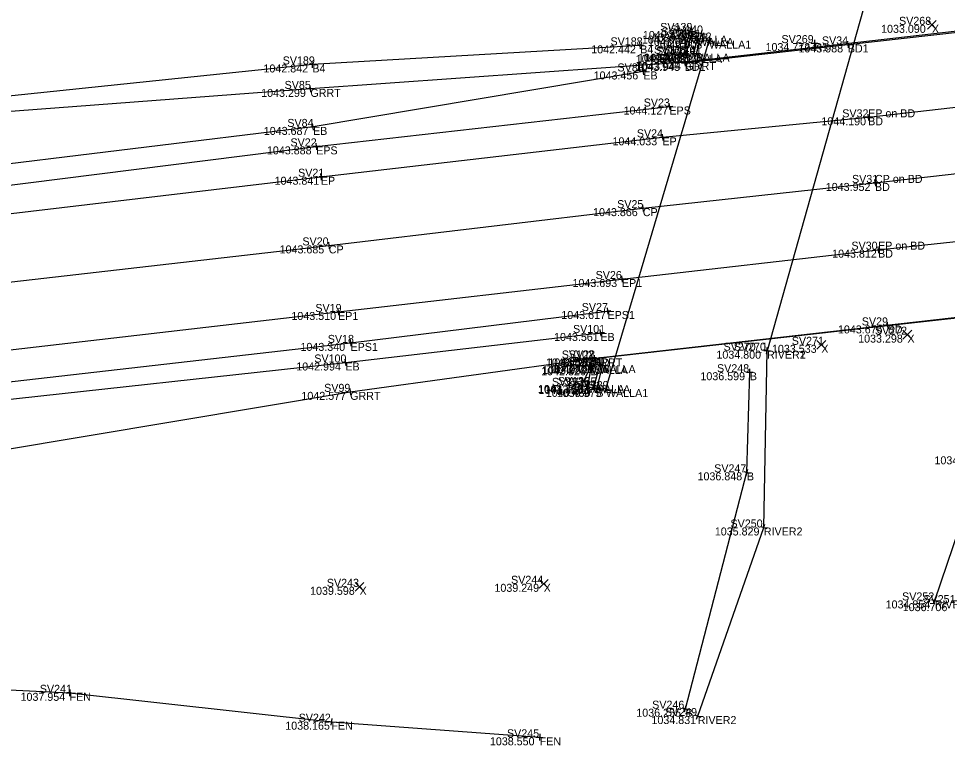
# Model space of a CAD drawing. Extents: x 1542529 to 1609210, y 587215 to 645373.
# Drawn here: x 1608791 to 1608930.2, y 645166.5 to 645275.5 of the extents above; entities that cross this region are included whole.
import ezdxf

# ---------------------------------------------------------------- set-up
doc = ezdxf.new("R2010")
doc.units = 0
for name, color, linetype in [('BR_X_SV_Abut', 7, 'Continuous'), ('BR_X_SV_Abut_Text', 7, 'Continuous'), ('BR_X_SV_Deck_Top', 7, 'Continuous'), ('BR_X_SV_Deck_Top_Text', 7, 'Continuous'), ('HY_X_Water_Edge', 7, 'Continuous'), ('PV_X_COP', 7, 'Continuous'), ('PV_X_EOP', 7, 'Continuous'), ('PV_X_Shoulder', 7, 'Continuous'), ('PV_X_Shoulder_Aggregate', 7, 'Continuous'), ('RD_X_Fence', 7, 'Continuous'), ('RD_X_GR_Rt', 7, 'Continuous'), ('SV_X_Break_Lines', 7, 'Continuous'), ('SV_X_Random_Point', 7, 'Continuous'), ('SV_X_Shot_Marker', 7, 'Continuous'), ('SV_X_Text_Comment', 7, 'Continuous'), ('SV_X_Text_Elevation', 7, 'Continuous'), ('SV_X_Text_Name', 7, 'Continuous')]:
    doc.layers.add(name, color=color, linetype=linetype)

msp = doc.modelspace()

# ---------------------------------------------------------------- linework, layer by layer
at = {"layer": 'BR_X_SV_Abut'}
for points in [[(1608879.02, 645219.91), (1608894.47, 645272.17)], [(1608890.97, 645270.03), (1608891.79, 645272.91), (1608892.73, 645272.57), (1608892.12, 645270.19)], [(1608878.03, 645223.49), (1608877.23, 645220.46), (1608876.34, 645220.52), (1608876.85, 645223.37)]]:
    msp.add_lwpolyline(points, dxfattribs=at)
at = {"layer": 'BR_X_SV_Abut_Text'}
for p, q in [((1608891.31, 645273.05), (1608892.27, 645272.78)), ((1608891.65, 645272.43), (1608891.92, 645273.39)), ((1608892.9, 645273.04), (1608892.56, 645272.1)), ((1608891.79, 645272.91), (1608891.79, 645272.91)), ((1608892.26, 645272.74), (1608893.2, 645272.4)), ((1608892.73, 645272.57), (1608892.73, 645272.57)), ((1608893.99, 645272.31), (1608894.95, 645272.03)), ((1608894.33, 645271.69), (1608894.61, 645272.65)), ((1608894.47, 645272.17), (1608894.47, 645272.17)), ((1608890.49, 645270.17), (1608891.45, 645269.89)), ((1608890.83, 645269.55), (1608891.1, 645270.51)), ((1608892.6, 645270.07), (1608891.64, 645270.32)), ((1608892.24, 645270.68), (1608892, 645269.71)), ((1608892.12, 645270.19), (1608892.12, 645270.19)), ((1608890.97, 645270.03), (1608890.97, 645270.03)), ((1608876.36, 645223.46), (1608877.34, 645223.28)), ((1608876.76, 645222.88), (1608876.94, 645223.86)), ((1608876.85, 645223.37), (1608876.85, 645223.37)), ((1608878.51, 645223.36), (1608877.54, 645223.62)), ((1608878.15, 645223.97), (1608877.9, 645223.01)), ((1608878.03, 645223.49), (1608878.03, 645223.49)), ((1608876.84, 645220.49), (1608875.84, 645220.54)), ((1608876.31, 645220.02), (1608876.37, 645221.01)), ((1608876.34, 645220.52), (1608876.34, 645220.52)), ((1608877.72, 645220.34), (1608876.75, 645220.59)), ((1608877.36, 645220.95), (1608877.11, 645219.98)), ((1608877.23, 645220.46), (1608877.23, 645220.46)), ((1608878.54, 645220.05), (1608879.5, 645219.77)), ((1608878.88, 645219.43), (1608879.16, 645220.39)), ((1608879.02, 645219.91), (1608879.02, 645219.91))]:
    msp.add_line(p, q, dxfattribs=at)
at = {"layer": 'BR_X_SV_Deck_Top'}
for points in [[(1608890.83, 645268.82), (1608915.28, 645271.59), (1608953.53, 645275.9), (1608984.83, 645279.39)], [(1608887.49, 645257.66), (1608918.33, 645260.66), (1608954.65, 645264.83), (1608980.54, 645267.46)], [(1608884.55, 645247.04), (1608919.35, 645250.82), (1608955.34, 645254.95), (1608977.96, 645256.77)], [(1608881.41, 645236.41), (1608919.82, 645240.81), (1608956.22, 645244.69), (1608975.06, 645246.73)], [(1608877.31, 645224.5), (1608921.25, 645229.45), (1608957.31, 645233.44), (1608971.94, 645235.23)]]:
    msp.add_lwpolyline(points, dxfattribs=at)
at = {"layer": 'BR_X_SV_Deck_Top_Text'}
for p, q in [((1608914.78, 645271.53), (1608915.78, 645271.65)), ((1608915.22, 645272.09), (1608915.34, 645271.09)), ((1608915.28, 645271.59), (1608915.28, 645271.59)), ((1608890.33, 645268.77), (1608891.32, 645268.88)), ((1608890.77, 645269.32), (1608890.88, 645268.33)), ((1608890.83, 645268.82), (1608890.83, 645268.82)), ((1608917.83, 645260.61), (1608918.83, 645260.71)), ((1608918.28, 645261.15), (1608918.38, 645260.16)), ((1608918.33, 645260.66), (1608918.33, 645260.66)), ((1608918.86, 645250.77), (1608919.85, 645250.88)), ((1608919.3, 645251.32), (1608919.41, 645250.32)), ((1608919.35, 645250.82), (1608919.35, 645250.82)), ((1608919.76, 645241.31), (1608919.87, 645240.31)), ((1608919.32, 645240.75), (1608920.31, 645240.87)), ((1608919.82, 645240.81), (1608919.82, 645240.81)), ((1608921.19, 645229.94), (1608921.3, 645228.95)), ((1608920.75, 645229.39), (1608921.74, 645229.5)), ((1608921.25, 645229.45), (1608921.25, 645229.45)), ((1608876.82, 645224.44), (1608877.81, 645224.55)), ((1608877.26, 645225), (1608877.37, 645224)), ((1608877.31, 645224.5), (1608877.31, 645224.5))]:
    msp.add_line(p, q, dxfattribs=at)
at = {"layer": 'HY_X_Water_Edge'}
for points in [[(1608927.27, 645323.87), (1608921.03, 645295.76), (1608920.78, 645288.24), (1608903.17, 645225.66)], [(1608928.31, 645188.21), (1608935.69, 645209.82), (1608940.9, 645230.56)], [(1608892.78, 645170.87), (1608902.69, 645199.15), (1608903.17, 645225.66)]]:
    msp.add_lwpolyline(points, dxfattribs=at)
at = {"layer": 'PV_X_COP'}
msp.add_lwpolyline([(1608671.55, 645219.6), (1608727.32, 645227.68), (1608782.03, 645235.07), (1608837.47, 645241.45), (1608884.55, 645247.04)], dxfattribs=at)
at = {"layer": 'PV_X_EOP'}
for points in [[(1608669.93, 645230.13), (1608725.82, 645238.07), (1608781.37, 645245.23), (1608836.27, 645251.75), (1608887.49, 645257.66)], [(1608672.74, 645209.93), (1608728.42, 645217.7), (1608783.22, 645225.06), (1608838.86, 645231.47), (1608881.41, 645236.41)]]:
    msp.add_lwpolyline(points, dxfattribs=at)
at = {"layer": 'PV_X_Shoulder'}
for points in [[(1608669.52, 645234.3), (1608724.97, 645242.37), (1608781.24, 645249.44), (1608835.57, 645256.3), (1608888.53, 645262.28)], [(1608672.97, 645206.8), (1608729.46, 645213.9), (1608783.39, 645220.28), (1608840.72, 645226.83), (1608879.25, 645231.61)]]:
    msp.add_lwpolyline(points, dxfattribs=at)
at = {"layer": 'PV_X_Shoulder_Aggregate'}
for points in [[(1608884.62, 645267.54), (1608835.11, 645259.22), (1608780.98, 645252.63), (1608724.64, 645244.99), (1608669.45, 645236.36)], [(1608673.57, 645203.81), (1608730.4, 645211.29), (1608784.18, 645217.8), (1608839.95, 645223.89), (1608878.18, 645228.32)]]:
    msp.add_lwpolyline(points, dxfattribs=at)
at = {"layer": 'RD_X_Fence'}
msp.add_lwpolyline([(1608683.09, 645172.08), (1608726.62, 645177.95), (1608798.6, 645174.35), (1608837.85, 645170.02), (1608869.08, 645167.68)], dxfattribs=at)
at = {"layer": 'RD_X_GR_Rt'}
for p, q in [((1608987.41, 645279.9), (1608890.95, 645268.94)), ((1608890.95, 645268.94), (1608834.71, 645264.92)), ((1608834.71, 645264.92), (1608779.9, 645260.78)), ((1608876.93, 645224.49), (1608971.87, 645235.28)), ((1608840.67, 645219.49), (1608876.93, 645224.49)), ((1608785.12, 645210.19), (1608840.67, 645219.49))]:
    msp.add_line(p, q, dxfattribs=at)
at = {"layer": 'SV_X_Break_Lines'}
for points in [[(1608890.69, 645270.2), (1608891.62, 645273.61), (1608893.3, 645273.23), (1608892.55, 645270.19)], [(1608884.15, 645271.45), (1608835, 645268.59), (1608778.42, 645262.67), (1608720.98, 645258.97), (1608666.54, 645249.78)], [(1608878.52, 645223.49), (1608877.58, 645219.94), (1608875.37, 645220.39), (1608876.7, 645223.17)], [(1608890.93, 645171.97), (1608900.15, 645207.42), (1608900.59, 645222.43)]]:
    msp.add_lwpolyline(points, dxfattribs=at)
at = {"layer": 'SV_X_Random_Point'}
for p, q in [((1608927.22, 645273.86), (1608928.55, 645275.2)), ((1608927.22, 645275.2), (1608928.55, 645273.86)), ((1608923.55, 645227.4), (1608924.89, 645228.74)), ((1608923.55, 645228.74), (1608924.89, 645227.4)), ((1608910.64, 645225.87), (1608911.97, 645227.21)), ((1608910.64, 645227.21), (1608911.97, 645225.87)), ((1608841.4, 645189.58), (1608842.74, 645190.91)), ((1608841.4, 645190.91), (1608842.74, 645189.58)), ((1608869.01, 645190.03), (1608870.35, 645191.37)), ((1608869.01, 645191.37), (1608870.35, 645190.03))]:
    msp.add_line(p, q, dxfattribs=at)
at = {"layer": 'SV_X_Shot_Marker'}
for p, q in [((1608891.14, 645273.74), (1608892.11, 645273.47)), ((1608891.49, 645273.12), (1608891.76, 645274.09)), ((1608891.62, 645273.61), (1608891.62, 645273.61)), ((1608892.82, 645273.34), (1608893.79, 645273.12)), ((1608893.41, 645273.72), (1608893.19, 645272.74)), ((1608893.3, 645273.23), (1608893.3, 645273.23)), ((1608884.18, 645270.95), (1608884.12, 645271.95)), ((1608909.77, 645271.79), (1608910.77, 645271.79)), ((1608910.27, 645272.29), (1608910.27, 645271.29)), ((1608910.27, 645271.79), (1608910.27, 645271.79)), ((1608884.65, 645271.48), (1608883.65, 645271.42)), ((1608884.15, 645271.45), (1608884.15, 645271.45)), ((1608890.21, 645270.33), (1608891.18, 645270.06)), ((1608890.56, 645269.71), (1608890.82, 645270.68)), ((1608890.69, 645270.2), (1608890.69, 645270.2)), ((1608893.04, 645270.07), (1608892.07, 645270.3)), ((1608892.67, 645270.67), (1608892.43, 645269.7)), ((1608892.55, 645270.19), (1608892.55, 645270.19)), ((1608835.03, 645268.09), (1608834.97, 645269.09)), ((1608891.45, 645268.97), (1608890.45, 645268.9)), ((1608890.98, 645268.44), (1608890.91, 645269.44)), ((1608890.95, 645268.94), (1608890.95, 645268.94)), ((1608835.5, 645268.62), (1608834.5, 645268.56)), ((1608835, 645268.59), (1608835, 645268.59)), ((1608885.12, 645267.63), (1608884.13, 645267.46)), ((1608884.7, 645267.05), (1608884.54, 645268.04)), ((1608884.62, 645267.54), (1608884.62, 645267.54)), ((1608835.21, 645264.95), (1608834.21, 645264.88)), ((1608834.75, 645264.42), (1608834.67, 645265.42)), ((1608834.71, 645264.92), (1608834.71, 645264.92)), ((1608888.03, 645262.22), (1608889.03, 645262.34)), ((1608888.47, 645262.78), (1608888.59, 645261.78)), ((1608888.53, 645262.28), (1608888.53, 645262.28)), ((1608835.6, 645259.3), (1608834.62, 645259.14)), ((1608835.19, 645258.73), (1608835.03, 645259.72)), ((1608835.11, 645259.22), (1608835.11, 645259.22)), ((1608886.99, 645257.61), (1608887.99, 645257.71)), ((1608887.44, 645258.15), (1608887.54, 645257.16)), ((1608887.49, 645257.66), (1608887.49, 645257.66)), ((1608835.07, 645256.24), (1608836.07, 645256.36)), ((1608835.51, 645256.8), (1608835.63, 645255.8)), ((1608835.57, 645256.3), (1608835.57, 645256.3)), ((1608836.21, 645252.24), (1608836.33, 645251.25)), ((1608835.77, 645251.69), (1608836.76, 645251.81)), ((1608836.27, 645251.75), (1608836.27, 645251.75)), ((1608884.06, 645246.99), (1608885.05, 645247.1)), ((1608884.5, 645247.54), (1608884.61, 645246.55)), ((1608884.55, 645247.04), (1608884.55, 645247.04)), ((1608836.98, 645241.39), (1608837.97, 645241.51)), ((1608837.42, 645241.95), (1608837.53, 645240.95)), ((1608837.47, 645241.45), (1608837.47, 645241.45)), ((1608881.35, 645236.91), (1608881.46, 645235.92)), ((1608880.91, 645236.36), (1608881.9, 645236.47)), ((1608881.41, 645236.41), (1608881.41, 645236.41)), ((1608838.37, 645231.41), (1608839.36, 645231.53)), ((1608838.81, 645231.97), (1608838.92, 645230.97)), ((1608838.86, 645231.47), (1608838.86, 645231.47)), ((1608878.75, 645231.55), (1608879.74, 645231.67)), ((1608879.19, 645232.11), (1608879.31, 645231.12)), ((1608879.25, 645231.61), (1608879.25, 645231.61)), ((1608878.12, 645228.82), (1608878.24, 645227.82)), ((1608840.66, 645227.33), (1608840.77, 645226.33)), ((1608877.68, 645228.26), (1608878.68, 645228.38)), ((1608878.18, 645228.32), (1608878.18, 645228.32)), ((1608840.22, 645226.77), (1608841.21, 645226.89)), ((1608840.72, 645226.83), (1608840.72, 645226.83)), ((1608902.67, 645225.67), (1608903.67, 645225.65)), ((1608903.65, 645225.52), (1608902.68, 645225.79)), ((1608903.3, 645226.14), (1608903.03, 645225.18)), ((1608903.16, 645225.16), (1608903.17, 645226.16)), ((1608903.17, 645225.66), (1608903.17, 645225.66)), ((1608903.17, 645225.66), (1608903.17, 645225.66)), ((1608839.89, 645224.38), (1608840, 645223.39)), ((1608876.43, 645224.43), (1608877.43, 645224.55)), ((1608876.87, 645224.99), (1608876.99, 645223.99)), ((1608876.93, 645224.49), (1608876.93, 645224.49)), ((1608839.45, 645223.83), (1608840.44, 645223.94)), ((1608839.95, 645223.89), (1608839.95, 645223.89)), ((1608876.25, 645223.38), (1608877.15, 645222.95)), ((1608876.49, 645222.72), (1608876.92, 645223.62)), ((1608876.7, 645223.17), (1608876.7, 645223.17)), ((1608879, 645223.36), (1608878.04, 645223.62)), ((1608878.65, 645223.97), (1608878.39, 645223.01)), ((1608878.52, 645223.49), (1608878.52, 645223.49)), ((1608900.57, 645221.93), (1608900.6, 645222.93)), ((1608900.09, 645222.45), (1608901.08, 645222.42)), ((1608900.59, 645222.43), (1608900.59, 645222.43)), ((1608875.86, 645220.29), (1608874.88, 645220.49)), ((1608875.27, 645219.9), (1608875.48, 645220.88)), ((1608875.37, 645220.39), (1608875.37, 645220.39)), ((1608878.06, 645219.81), (1608877.09, 645220.06)), ((1608877.71, 645220.42), (1608877.45, 645219.45)), ((1608840.18, 645219.42), (1608841.17, 645219.56)), ((1608840.6, 645219.99), (1608840.74, 645218.99)), ((1608840.67, 645219.49), (1608840.67, 645219.49)), ((1608877.58, 645219.94), (1608877.58, 645219.94)), ((1608899.67, 645207.54), (1608900.64, 645207.29)), ((1608900.03, 645206.93), (1608900.28, 645207.9)), ((1608900.15, 645207.42), (1608900.15, 645207.42)), ((1608902.22, 645199.31), (1608903.16, 645198.98)), ((1608902.53, 645198.67), (1608902.86, 645199.62)), ((1608902.69, 645199.15), (1608902.69, 645199.15)), ((1608927.83, 645188.37), (1608928.78, 645188.05)), ((1608928.15, 645187.74), (1608928.47, 645188.69)), ((1608928.31, 645188.21), (1608928.31, 645188.21)), ((1608798.1, 645174.37), (1608799.1, 645174.32)), ((1608798.62, 645174.84), (1608798.57, 645173.85)), ((1608798.6, 645174.35), (1608798.6, 645174.35)), ((1608890.44, 645172.1), (1608891.41, 645171.85)), ((1608890.8, 645171.49), (1608891.05, 645172.46)), ((1608890.93, 645171.97), (1608890.93, 645171.97)), ((1608892.61, 645170.4), (1608892.94, 645171.35)), ((1608837.35, 645170.07), (1608838.34, 645169.96)), ((1608837.9, 645170.51), (1608837.79, 645169.52)), ((1608837.85, 645170.02), (1608837.85, 645170.02)), ((1608892.3, 645171.04), (1608893.25, 645170.71)), ((1608892.78, 645170.87), (1608892.78, 645170.87)), ((1608868.58, 645167.72), (1608869.58, 645167.64)), ((1608869.12, 645168.18), (1608869.04, 645167.18)), ((1608869.08, 645167.68), (1608869.08, 645167.68))]:
    msp.add_line(p, q, dxfattribs=at)

# ---------------------------------------------------------------- texts
at = {"layer": 'BR_X_SV_Abut_Text'}
for s, p in [('SV144', (1608887.35, 645272.91)), ('SV145', (1608888.28, 645272.57)), ('SV142', (1608890.03, 645272.17)), ('1043.655', (1608884.4, 645271.71)), ('1043.649', (1608885.32, 645271.37)), ('1040.008', (1608886.77, 645270.97)), ('WALLA', (1608891.79, 645271.71)), ('WALLA', (1608892.73, 645271.37)), ('WALLA1', (1608894.47, 645270.97)), ('1043.723', (1608884.79, 645268.99)), ('SV143', (1608886.52, 645270.03)), ('SV146', (1608887.6, 645270.19)), ('WALLA', (1608892.12, 645268.99)), ('1043.760', (1608883.49, 645268.83)), ('WALLA', (1608890.97, 645268.83)), ('SV137', (1608872.39, 645223.37)), ('SV134', (1608873.58, 645223.49)), ('1043.389', (1608869.45, 645222.17)), ('1043.400', (1608870.43, 645222.29)), ('WALLA', (1608876.85, 645222.17)), ('WALLA', (1608878.03, 645222.29)), ('SV136', (1608871.8, 645220.52)), ('SV135', (1608872.77, 645220.46)), ('1043.308', (1608868.83, 645219.32)), ('1043.333', (1608869.83, 645219.26)), ('SV129', (1608874.59, 645219.91)), ('WALLA', (1608876.34, 645219.32)), ('WALLA', (1608877.23, 645219.26)), ('1039.975', (1608871.64, 645218.71)), ('WALLA1', (1608879.02, 645218.71))]:
    msp.add_text(s, height=1.2, dxfattribs=at).set_placement(p)
at = {"layer": 'BR_X_SV_Deck_Top_Text'}
for s, p in [('1043.988', (1608907.88, 645270.39)), ('SV34', (1608911.4, 645271.59)), ('BD1', (1608915.28, 645270.39)), ('1043.945', (1608883.43, 645267.62)), ('SV33', (1608886.93, 645268.82)), ('BD1', (1608890.83, 645267.62)), ('SV32', (1608914.45, 645260.66)), ('EP on BD', (1608918.33, 645260.66)), ('1044.190', (1608911.32, 645259.46)), ('BD', (1608918.33, 645259.46)), ('1043.952', (1608911.98, 645249.62)), ('SV31', (1608915.91, 645250.82)), ('CP on BD', (1608919.35, 645250.82)), ('BD', (1608919.35, 645249.62)), ('SV30', (1608915.82, 645240.81)), ('EP on BD', (1608919.82, 645240.81)), ('1043.812', (1608912.93, 645239.61)), ('BD', (1608919.82, 645239.61)), ('SV29', (1608917.38, 645229.45)), ('1043.676', (1608913.8, 645228.25)), ('BD', (1608921.25, 645228.25)), ('SV28', (1608873.45, 645224.5)), ('1043.551', (1608870.39, 645223.3)), ('BD', (1608877.31, 645223.3))]:
    msp.add_text(s, height=1.2, dxfattribs=at).set_placement(p)
at = {"layer": 'SV_X_Text_Comment'}
for s, p in [('X', (1608927.88, 645273.33)), ('B', (1608891.62, 645272.41)), ('B', (1608893.3, 645272.03)), ('R1', (1608910.27, 645270.59)), ('B4', (1608884.15, 645270.25)), ('B', (1608890.69, 645269)), ('B', (1608892.55, 645268.99)), ('GRRT', (1608890.95, 645267.74)), ('B4', (1608835, 645267.39)), ('EB', (1608884.62, 645266.34)), ('GRRT', (1608834.71, 645263.72)), ('EPS', (1608888.53, 645261.08)), ('EB', (1608835.11, 645258.02)), ('EP', (1608887.49, 645256.46)), ('EPS', (1608835.57, 645255.1)), ('EP', (1608836.27, 645250.55)), ('CP', (1608884.55, 645245.84)), ('CP', (1608837.47, 645240.25)), ('EP1', (1608881.41, 645235.21)), ('EP1', (1608838.86, 645230.27)), ('EPS1', (1608879.25, 645230.41)), ('EB', (1608878.18, 645227.12)), ('X', (1608924.22, 645226.87)), ('EPS1', (1608840.72, 645225.63)), ('RIVER2', (1608903.17, 645224.46)), ('RIVER1', (1608903.17, 645224.46)), ('X', (1608911.3, 645225.34)), ('GRRT', (1608876.93, 645223.29)), ('EB', (1608839.95, 645222.69)), ('B', (1608876.7, 645221.97)), ('B', (1608878.52, 645222.29)), ('B', (1608900.59, 645221.23)), ('B', (1608875.37, 645219.19)), ('GRRT', (1608840.67, 645218.29)), ('B', (1608877.58, 645218.74)), ('B', (1608900.15, 645206.22)), ('RIVER2', (1608902.69, 645197.95)), ('X', (1608842.07, 645189.05)), ('X', (1608869.68, 645189.5)), ('RIVER3', (1608928.31, 645187.01)), ('FEN', (1608798.6, 645173.15)), ('B', (1608890.93, 645170.77)), ('FEN', (1608837.85, 645168.82)), ('RIVER2', (1608892.78, 645169.67)), ('FEN', (1608869.08, 645166.48))]:
    msp.add_text(s, height=1.2, dxfattribs=at).set_placement(p)
at = {"layer": 'SV_X_Text_Elevation'}
for s, p in [('1033.090', (1608920.27, 645273.33)), ('1040.416', (1608884.55, 645272.41)), ('1039.925', (1608885.92, 645272.03)), ('1034.772', (1608902.94, 645270.59)), ('1042.442', (1608876.81, 645270.25)), ('1041.978', (1608883.81, 645269)), ('1040.172', (1608885.59, 645268.99)), ('1043.944', (1608883.56, 645267.74)), ('1042.842', (1608827.67, 645267.39)), ('1043.456', (1608877.17, 645266.34)), ('1043.299', (1608827.33, 645263.72)), ('1044.127', (1608881.66, 645261.08)), ('1043.687', (1608827.72, 645258.02)), ('1044.033', (1608880, 645256.46)), ('1043.888', (1608828.19, 645255.1)), ('1043.841', (1608829.34, 645250.55)), ('1043.866', (1608877.09, 645245.84)), ('1043.685', (1608830.09, 645240.25)), ('1043.693', (1608874, 645235.21)), ('1043.510', (1608831.86, 645230.27)), ('1043.617', (1608872.33, 645230.41)), ('1043.561', (1608871.24, 645227.12)), ('1033.298', (1608916.83, 645226.87)), ('1043.340', (1608833.22, 645225.63)), ('1034.800', (1608895.58, 645224.46)), ('1034.800', (1608895.58, 645224.46)), ('1033.533', (1608903.91, 645225.34)), ('1043.195', (1608870.01, 645223.29)), ('1042.994', (1608832.59, 645222.69)), ('1042.826', (1608869.31, 645221.97)), ('1040.020', (1608870.86, 645222.29)), ('1036.599', (1608893.18, 645221.23)), ('1041.416', (1608868.89, 645219.19)), ('1042.577', (1608833.36, 645218.29)), ('1040.480', (1608870, 645218.74)), ('1034.526', (1608928.27, 645208.62)), ('1036.848', (1608892.75, 645206.22)), ('1035.829', (1608895.34, 645197.95)), ('1039.598', (1608834.66, 645189.05)), ('1039.249', (1608862.3, 645189.5)), ('1034.854', (1608920.95, 645187.01)), ('1036.706', (1608923.51, 645186.6)), ('1037.954', (1608791.25, 645173.15)), ('1036.255', (1608883.57, 645170.77)), ('1038.165', (1608830.94, 645168.82)), ('1034.831', (1608885.84, 645169.67)), ('1038.550', (1608861.62, 645166.48))]:
    msp.add_text(s, height=1.2, dxfattribs=at).set_placement(p)
at = {"layer": 'SV_X_Text_Name'}
for s, p in [('SV268', (1608922.96, 645274.53)), ('SV139', (1608887.16, 645273.61)), ('SV140', (1608888.75, 645273.23)), ('SV269', (1608905.34, 645271.79)), ('SV188', (1608879.7, 645271.45)), ('SV138', (1608886.22, 645270.2)), ('SV141', (1608888.55, 645270.19)), ('SV189', (1608830.55, 645268.59)), ('SV82', (1608887.08, 645268.94)), ('SV83', (1608880.75, 645267.54)), ('SV85', (1608830.84, 645264.92)), ('SV23', (1608884.68, 645262.28)), ('SV84', (1608831.25, 645259.22)), ('SV24', (1608883.65, 645257.66)), ('SV22', (1608831.72, 645256.3)), ('SV21', (1608832.86, 645251.75)), ('SV25', (1608880.7, 645247.04)), ('SV20', (1608833.51, 645241.45)), ('SV26', (1608877.47, 645236.41)), ('SV19', (1608835.45, 645231.47)), ('SV27', (1608875.39, 645231.61)), ('SV101', (1608874.08, 645228.32)), ('SV272', (1608919.35, 645228.07)), ('SV18', (1608837.31, 645226.83)), ('SV271', (1608906.88, 645226.54)), ('SV102', (1608872.39, 645224.49)), ('SV270_1', (1608896.65, 645225.66)), ('SV270', (1608898.19, 645225.66)), ('SV100', (1608835.29, 645223.89)), ('SV133', (1608872.24, 645223.17)), ('SV130', (1608873.96, 645223.49)), ('SV248', (1608895.67, 645222.43)), ('SV132', (1608870.92, 645220.39)), ('SV99', (1608836.77, 645219.49)), ('SV131', (1608873.57, 645219.94)), ('SV247', (1608895.25, 645207.42)), ('SV250', (1608897.69, 645199.15)), ('SV243', (1608837.17, 645190.25)), ('SV244', (1608864.79, 645190.7)), ('SV252', (1608923.42, 645188.21)), ('SV251', (1608926.61, 645187.8)), ('SV241', (1608794.14, 645174.35)), ('SV246', (1608885.95, 645171.97)), ('SV249', (1608887.86, 645170.87)), ('SV242', (1608832.95, 645170.02)), ('SV245', (1608864.18, 645167.68))]:
    msp.add_text(s, height=1.2, dxfattribs=at).set_placement(p)

doc.saveas('drawing.dxf')
